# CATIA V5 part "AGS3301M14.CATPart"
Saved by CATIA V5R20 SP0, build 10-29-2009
Part number: AGS3301M14
Definition: NONE
Nomenclature: AGS3301M14
Source: Unknown
Description: AGS3301M14
Bounding box of the stored display mesh (mm): x -20 to 25, y -10.811 to 10.811, z -8.8 to 8.8
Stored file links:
  C:\Users\Utente\Desktop\IO LAVORO\3D X SITO CF\X SITO\PLASTICA\AGS\AGS3301M14.CATPart
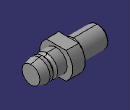
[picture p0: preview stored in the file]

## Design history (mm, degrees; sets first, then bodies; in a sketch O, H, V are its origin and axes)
Body1 "AGS3301M14" (main body)
  Solid1: solid without history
